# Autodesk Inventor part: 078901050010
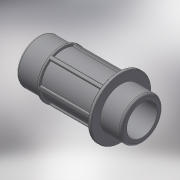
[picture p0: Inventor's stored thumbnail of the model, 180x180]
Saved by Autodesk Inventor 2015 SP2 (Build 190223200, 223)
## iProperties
Created: 2018-02
Part Number: 078901050010
Material: Generic
Description: PLASSON THREADED MALE ADAPTOR 50-1"
Document SubType Name: Modeling
Designer: KIM
Density: 1 g/cm^3
Appearance: Default
Author: KIM
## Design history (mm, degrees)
derived "078901.ipt"
feature "Solid1::078901.ipt"
tag "TaggingFeature1"
body "Solid1"
other parameters: "d4" = 1.66245, "d14" = 2.65992, "d15" = 1.32996, "d17" = 0, "d20" = 360 deg, "d41" = 33.249, "d45" = 36.5739, "d46" = 23.2743, "d47" = 2, "d77" = 102, "d85" = 0.33249, "d91" = 20.4, "d103" = 23.46, "d104" = 69, "d105" = 0.33249, "R_" = 33.249, "E_" = 69, "l_" = 102
